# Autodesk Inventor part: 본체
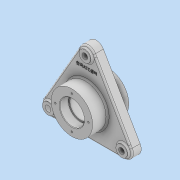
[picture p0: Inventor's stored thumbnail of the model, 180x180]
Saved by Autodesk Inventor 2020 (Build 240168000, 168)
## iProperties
Created: 2023-04
Part Number: 본체
Material: 일반
Document SubType Name: Modeling
Designer: oem
Density: 1 g/cm^3
Appearance: 기본값
Author: oem
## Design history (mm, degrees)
sketch "스케치1" dims "d7" = 164
  geometry: L1 (0, 82)-(71.014, -41); L2 (71.014, -41)-(-71.014, -41); L3 (-71.014, -41)-(0, 82); L4 (-13.856, 90)-(-84.87, -33); L5 (84.87, -33)-(13.856, 90); L6 (-71.014, -57)-(71.014, -57); C1 r 40 at (0, 0); C2 r 57 at (0, 0); A1 r 16 centre (-71.014, -41) between (-84.87, -33) and (-71.014, -57); A2 r 16 centre (71.014, -41) between (71.014, -57) and (84.87, -33); A3 r 16 centre (0, 82) between (13.856, 90) and (-13.856, 90); 5 further points
  constraints: 12 end point, 11 coincident, 6 point on circle, 5 centre point, 5 tangent, 2 vertical alignment, 1 horizontal, 9 other
  dimensions: "d0" = 80 diameter of C1; "d3" = 32 diameter of A1; "d4" = 32 diameter of A2; "d5" = 32 diameter of A3; "d8" = 114 diameter of C2
extrude "돌출1" new body sketch "스케치1" stored distance "d9" = 18; taper "d10" = 0 deg
sketch "스케치2"
  geometry: C1 r 40 at (0, 0) reference; 1 further point
extrude "돌출2" join sketch "스케치2" distance "d11" = 23; taper "d12" = 0 deg
sketch "스케치3"
  geometry: C1 r 40 at (0, 0) reference; C2 r 45 at (0, 0)
  constraints: 1 centre point, 1 coincident
  dimensions: "d13" = 90 diameter of C2
extrude "돌출3" join sketch "스케치3" distance "d14" = 5; taper "d15" = 0 deg
sketch "스케치4"
  geometry: C1 r 40 at (0, 0) reference; 1 further point
extrude "돌출4" join sketch "스케치4" distance "d16" = 29; taper "d17" = 0 deg
node "작업 평면1"
sketch "스케치5"
  geometry: C1 r 11 at (-71.014, -41); C2 r 11 at (71.014, -41); C3 r 11 at (0, 82); A1 r 16 centre (-71.014, -41) between (-84.87, -33) and (-71.014, -57) reference; A2 r 16 centre (71.014, -41) between (71.014, -57) and (84.87, -33) reference; A3 r 16 centre (0, 82) between (13.856, 90) and (-13.856, 90) reference; 1 further point
  constraints: 3 centre point, 3 coincident
  dimensions: "d19" = 22 diameter of C1; "d20" = 22 diameter of C2; "d21" = 22 diameter of C3
extrude "돌출5" join sketch "스케치5" stored distance "d22" = 29; taper "d23" = 0 deg
sketch "스케치6"
  geometry: C1 r 11 at (0, 0) reference; C2 r 11 at (-71.014, -123) reference; C3 r 11 at (71.014, -123) reference; 4 further points
  constraints: 3 coincident
hole "구멍1" sketch "스케치6" at (0, 0), (-71.014, -123), (71.014, -123) diameter "d24" = 11; stored, may be unused: countersink angle "d28" = 90 deg, drill point angle "d30" = 120 deg; dims "d25" = 6, "d26" = 4, "d27" = 2, "d29" = 20
sketch "스케치7"
  geometry: C1 r 40 at (0, 0) reference; C2 r 21 at (0, 0)
  constraints: 1 centre point, 1 coincident
  dimensions: "d31" = 42 diameter of C2
extrude "돌출6" cut sketch "스케치7" extent not by distance; stored distance "d32" = 0; taper "d33" = 0 deg
sketch "스케치8"
  geometry: C1 r 21 at (0, 0) reference; C2 r 40 at (0, 0) reference; C3 r 23.5 at (0, 0)
  constraints: 1 centre point, 1 coincident
  dimensions: "d34" = 47 diameter of C3
extrude "돌출7" cut sketch "스케치8" distance "d35" = 17; taper "d36" = 0 deg
sketch "스케치9"
  geometry: C1 r 40 at (0, 0) reference; C2 r 23.5 at (0, 0)
  constraints: 1 centre point, 1 coincident
  dimensions: "d37" = 47 diameter of C2
extrude "돌출8" cut sketch "스케치9" distance "d38" = 17; taper "d39" = 0 deg
sketch "스케치10"
  geometry: C1 r 23.5 at (0, 0) reference; C2 r 40 at (0, 0) reference; A1 r 32 centre (0, 0) between (0, 32) and (-32, 0); 2 further points
  constraints: 4 point on circle, 2 horizontal alignment, 2 vertical alignment, 1 centre point, 1 coincident
  dimensions: "d40" = 64 diameter of A1
hole "구멍2" sketch "스케치10" at (0, 32), (-32, 0), (0, -32), (32, 0) diameter "d41" = 3.242; stored, may be unused: countersink angle "d45" = 90 deg, drill point angle "d47" = 120 deg; dims "d42" = 8, "d43" = 4, "d44" = 2, "d46" = 10
sketch "스케치11"
  geometry: C1 r 40 at (0, 0) reference; C2 r 32 at (0, 0); C3 r 1.621 at (0, 32) reference; C4 r 1.621 at (0, -32) reference; C5 r 1.621 at (32, 0) reference; C6 r 1.621 at (-32, 0) reference; 4 further points
  constraints: 5 coincident, 1 centre point
  dimensions: "d48" = 64 diameter of C2
hole "구멍3" sketch "스케치11" at (0, 32), (0, -32), (32, 0), (-32, 0) diameter "d49" = 3.242; stored, may be unused: countersink angle "d53" = 90 deg, drill point angle "d55" = 120 deg; dims "d50" = 8, "d51" = 4, "d52" = 2, "d54" = 10
sketch "스케치12"
  geometry: L1 (-71.014, -57)-(71.014, -57) reference; L2 (-22.5, 65)-(22.5, 65); L3 (22.5, 65)-(22.5, 55); L4 (22.5, 55)-(-22.5, 55); L5 (-22.5, 55)-(-22.5, 65); L6 (-22.5, 60)-(22.5, 60); C1 r 40 at (0, 0) reference; 1 further point
  constraints: 3 midpoint, 2 end point, 1 parallel, 1 vertical alignment, 2 other
  dimensions: "d58" = 60 distance from line of C1.centre L6; "d59" = 10 distance of L2.end L3.end; "d60" = 45 distance between parallel lines of L3 L5
fillet "모깎기1" dims "d61" = 0.6
fillet "모깎기2" dims "d62" = 3
extrude "돌출9" join sketch "스케치12" distance "d63" = 0.5; taper "d64" = 0 deg
chamfer "모따기1" distance "d65" = 1; stored, may be unused: second distance "d66" = 2, angle "d67" = 45 deg
node "솔리드1"
feature "A9D066F2-1C7D-4E18-AEED-F7BC21143FA4" dims "d24" = 11, "d25" = 6, "d26" = 4, "d27" = 2, "d28" = 90 deg, "d29" = 20, "d30" = 120 deg
other parameters: "d18" = 4
